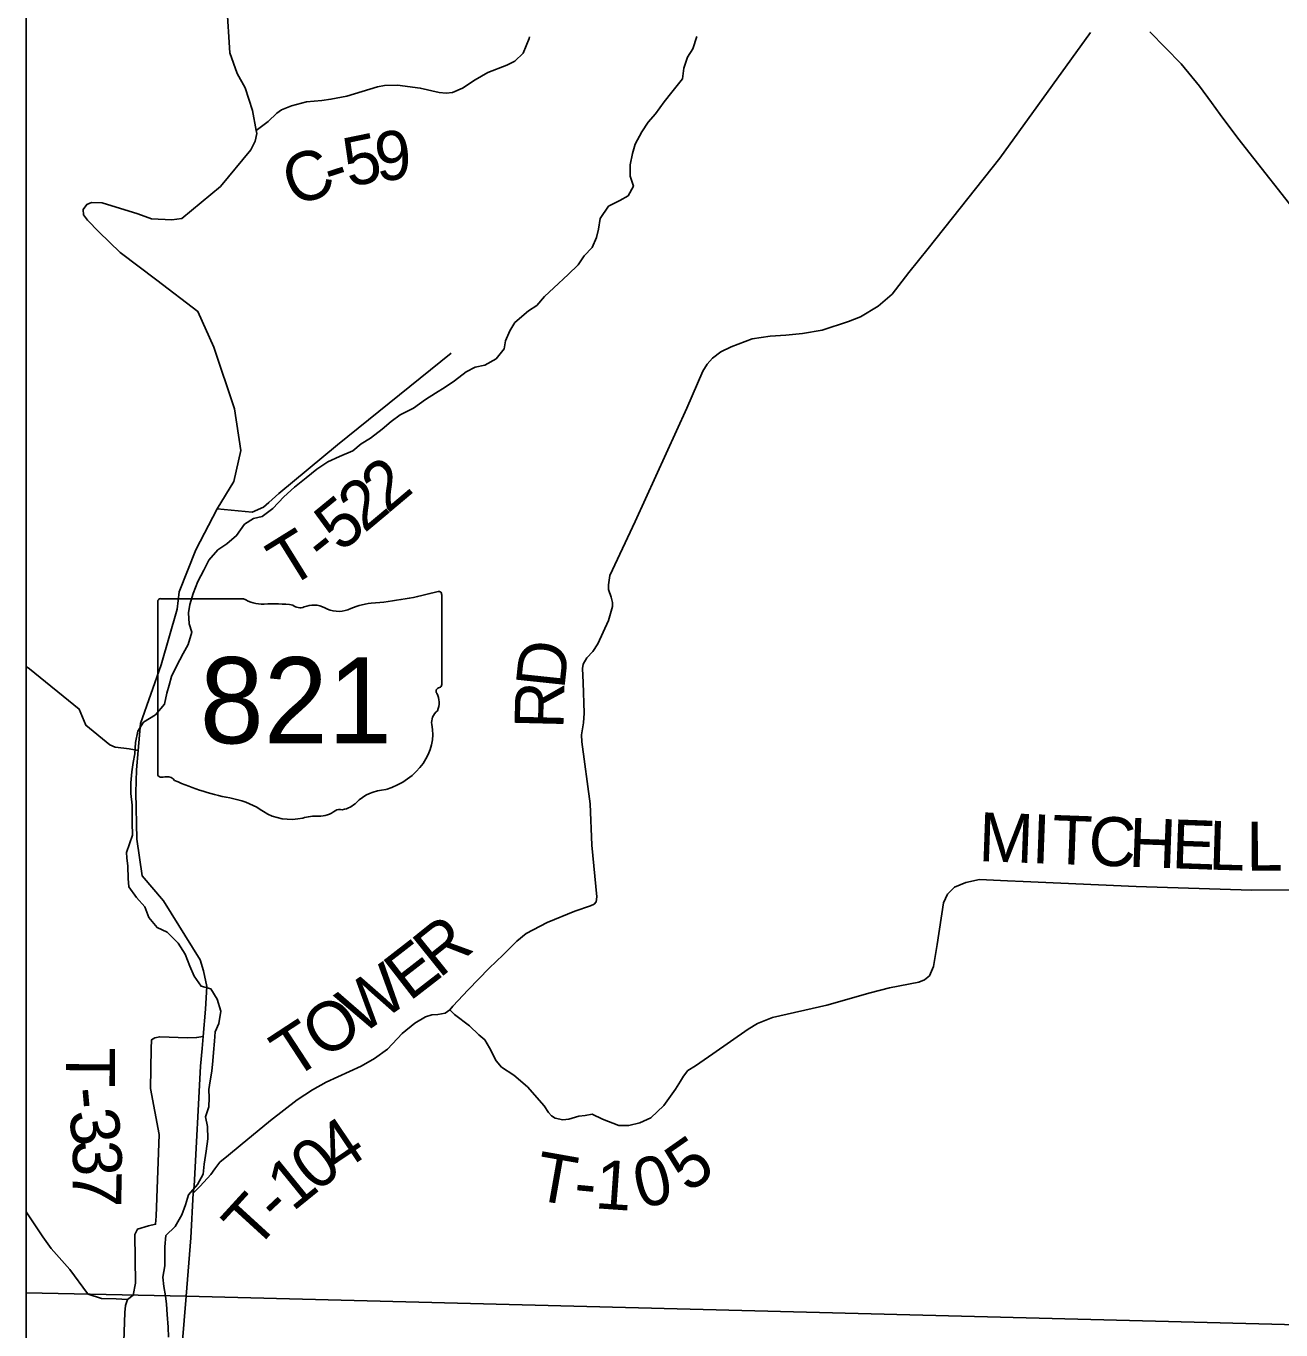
# Model space of a CAD drawing. Extents: x -22 to 431, y -18 to 160.
# Drawn here: x -8.719 to -7.263, y 17.085 to 18.598 of the extents above; entities that cross this region are included whole.
import ezdxf

# ---------------------------------------------------------------- set-up
doc = ezdxf.new("R2010")
doc.units = 0
for name, color, linetype in [('GM_X_Adjacent_County_Text', 7, 'Continuous'), ('GM_X_Airport_Location_Class_2', 7, 'Continuous'), ('GM_X_City_Street', 7, 'Continuous'), ('GM_X_City_Street_Text', 7, 'Continuous'), ('GM_X_Major_River_Text', 7, 'Continuous'), ('GM_X_Minor_River', 7, 'Continuous'), ('GM_X_Minor_River_Text', 7, 'Continuous'), ('GM_X_Rail_Line', 7, 'Continuous'), ('GM_X_Section', 7, 'Continuous')]:
    doc.layers.add(name, color=color, linetype=linetype)

msp = doc.modelspace()

# ---------------------------------------------------------------- linework, layer by layer
at = {"layer": 'GM_X_Adjacent_County_Text'}
for points in [[(-8.452, 18.4766), (-8.4382, 18.4871), (-8.4281, 18.4967), (-8.4228, 18.5009), (-8.4111, 18.5055), (-8.3937, 18.5102), (-8.3759, 18.5115), (-8.3653, 18.5131), (-8.3468, 18.5166), (-8.3113, 18.5275), (-8.303, 18.5291), (-8.2882, 18.5292), (-8.2617, 18.526), (-8.2397, 18.5209), (-8.2317, 18.5202), (-8.2242, 18.521), (-8.2125, 18.526), (-8.1978, 18.5356), (-8.1831, 18.5441), (-8.1612, 18.5526), (-8.1517, 18.5573), (-8.1423, 18.5664), (-8.1352, 18.5835), (-8.1348, 18.5855)], [(-6.8014, 18.0527), (-6.8014, 18.0528), (-6.8034, 18.0575), (-6.8042, 18.0624), (-6.8028, 18.0825), (-6.8187, 18.0839), (-6.946, 18.0918), (-6.9968, 18.095), (-7.0127, 18.099), (-7.0241, 18.1043), (-7.0435, 18.1223), (-7.1077, 18.2034), (-7.1677, 18.281), (-7.2342, 18.3681), (-7.3129, 18.468), (-7.3331, 18.4955), (-7.3434, 18.5091), (-7.3572, 18.5283), (-7.3786, 18.5543), (-7.4147, 18.5914)]]:
    msp.add_lwpolyline(points, dxfattribs=at)
at = {"layer": 'GM_X_Airport_Location_Class_2'}
for p, q in [((-8.5632, 17.9334), (-8.4666, 17.9334)), ((-8.2368, 17.9383), (-8.2368, 17.8337)), ((-8.5664, 17.9299), (-8.5664, 17.7298)), ((-8.5664, 17.7298), (-8.5664, 17.9299)), ((-8.5664, 17.7298), (-8.5664, 17.9299)), ((-8.2369, 17.8337), (-8.2368, 17.8337))]:
    msp.add_line(p, q, dxfattribs=at)
for centre, major_axis, start_param, end_param in [((-8.5626, 17.9304), (0.00382, 0), 1.712693, 3.28349), ((-8.4437, 17.9566), (0.037, 0), 4.042523, 4.731795), ((-8.3542, 18.2062), (0.3495, 0), 4.814394, 5.042369), ((-8.2405, 17.9388), (0.00367, 0), 6.141152, 7.989035), ((-8.4314, 17.821), (0.133, 0), 1.404758, 1.657858), ((-8.4012, 17.9314), (0.0107, 0), 3.836095, 5.185415), ((-8.3855, 17.9083), (0.0222, 0), 0.950623, 2.079405), ((-8.3568, 17.94), (0.0267, 0), 4.081561, 5.145723), ((-8.3096, 17.8723), (0.0703, 0), 1.699011, 2.107814), ((-8.2377, 17.826), (0.00568, 0), 1.883978, 3.671073), ((-8.2407, 17.8332), (0.00393, 0), 5.05454, 6.418171), ((-8.2738, 17.8127), (0.0341, 0), 5.934695, 6.695948), ((-8.2237, 17.7898), (0.0248, 0), 2.387724, 3.262537), ((-8.3346, 17.7765), (0.0874, 0), 5.101752, 6.440018), ((-8.5626, 17.7294), (0.00385, 0), 3.00124, 4.508301), ((-8.562, 17.7498), (0.0294, 0), 4.665946, 4.897461), ((-8.556, 17.7183), (0.0106, 0), 0.519207, 1.627899), ((-8.4222, 17.8981), (0.2524, 0), 4.195997, 4.488961), ((-8.2978, 17.6736), (0.0479, 0), 1.647645, 2.488434), ((-8.4974, 17.6399), (0.079, 0), 0.823519, 1.323587), ((-8.3584, 17.7104), (0.0282, 0), 4.937069, 5.64225), ((-8.412, 17.7173), (0.0501, 0), 4.026481, 4.996735), ((-8.3831, 17.6481), (0.0412, 0), 1.495662, 1.94098), ((-8.3794, 17.7023), (0.0267, 0), 4.691044, 5.507374), ((-8.3552, 17.6829), (0.00752, 0), 1.147584, 2.315152)]:
    msp.add_ellipse(centre, major_axis=major_axis, ratio=0.8, start_param=start_param, end_param=end_param, dxfattribs=at)
at = {"layer": 'GM_X_Major_River_Text'}
for p, q in [((-8.5332, 17.1237), (-8.7192, 17.1279)), ((-7.1011, 17.087), (-8.5332, 17.1237))]:
    msp.add_line(p, q, dxfattribs=at)
at = {"layer": 'GM_X_Minor_River'}
for points in [[(-8.6026, 17.6387), (-8.5958, 17.6591), (-8.5962, 17.6731), (-8.5959, 17.6834), (-8.5959, 17.6936), (-8.5975, 17.7072), (-8.5975, 17.7197), (-8.5964, 17.7326), (-8.5949, 17.7433), (-8.593, 17.7535), (-8.5923, 17.7664), (-8.5893, 17.7797), (-8.5829, 17.7899), (-8.5689, 17.7987), (-8.5584, 17.8109), (-8.5558, 17.8238), (-8.5531, 17.8332), (-8.5505, 17.8431), (-8.5445, 17.8549), (-8.537, 17.8697), (-8.5309, 17.8803), (-8.5268, 17.8944), (-8.5299, 17.9042), (-8.5307, 17.9171), (-8.5292, 17.9266), (-8.5254, 17.9395), (-8.5198, 17.9535), (-8.513, 17.9664), (-8.507, 17.9782), (-8.4968, 17.99), (-8.4862, 17.9972), (-8.4749, 18.0067), (-8.4655, 18.02), (-8.4553, 18.0265), (-8.4451, 18.0288), (-8.4326, 18.038), (-8.4201, 18.0517), (-8.4077, 18.0627), (-8.3941, 18.0737), (-8.3816, 18.0836), (-8.3691, 18.0924), (-8.3555, 18.0985), (-8.34, 18.105), (-8.3302, 18.113), (-8.3196, 18.1195), (-8.306, 18.1302), (-8.2955, 18.1389), (-8.2849, 18.1469), (-8.2694, 18.1545), (-8.2554, 18.1645), (-8.2441, 18.1721), (-8.2327, 18.1789), (-8.2221, 18.1862), (-8.2085, 18.1965), (-8.198, 18.2022), (-8.1866, 18.2045), (-8.1737, 18.2117), (-8.1643, 18.2232), (-8.1628, 18.2326), (-8.1576, 18.2444), (-8.1519, 18.2539), (-8.1361, 18.2676), (-8.1262, 18.2737), (-8.1175, 18.284), (-8.1066, 18.2942), (-8.09, 18.3098), (-8.0783, 18.3209), (-8.0715, 18.3315), (-8.0621, 18.341), (-8.0572, 18.3524), (-8.0549, 18.3623), (-8.0527, 18.3748), (-8.0433, 18.3889), (-8.03, 18.3957), (-8.0202, 18.4011), (-8.0142, 18.4121), (-8.018, 18.4238), (-8.018, 18.4371), (-8.0154, 18.45), (-8.0124, 18.461), (-8.0045, 18.4754), (-7.997, 18.4864), (-7.9887, 18.4963), (-7.9785, 18.51), (-7.9698, 18.5214), (-7.9574, 18.5366), (-7.9559, 18.5491), (-7.9514, 18.562), (-7.9454, 18.5715), (-7.9405, 18.5857)], [(-8.5539, 17.0762), (-8.5543, 17.088), (-8.5555, 17.1024), (-8.5563, 17.1145), (-8.5575, 17.1243), (-8.5594, 17.1349), (-8.5606, 17.1459), (-8.5583, 17.1592), (-8.558, 17.1687), (-8.558, 17.1812), (-8.5569, 17.1941), (-8.546, 17.2047), (-8.5385, 17.2184), (-8.5343, 17.2298), (-8.5306, 17.2416), (-8.5204, 17.2534), (-8.5136, 17.2655), (-8.5125, 17.2769), (-8.5103, 17.2921), (-8.5084, 17.3065), (-8.5085, 17.3209), (-8.5108, 17.3319), (-8.507, 17.3436), (-8.5067, 17.3542), (-8.5071, 17.3637), (-8.5056, 17.3736), (-8.5037, 17.385), (-8.5026, 17.3971), (-8.5015, 17.4066), (-8.5004, 17.4198), (-8.4997, 17.4305), (-8.4956, 17.4403), (-8.4933, 17.4548), (-8.4975, 17.4684), (-8.5048, 17.4805), (-8.5161, 17.4835), (-8.5241, 17.4952), (-8.5291, 17.5069), (-8.5344, 17.5209), (-8.5428, 17.5334), (-8.5553, 17.5463), (-8.5671, 17.5519), (-8.5766, 17.5633), (-8.5815, 17.5758), (-8.591, 17.5867), (-8.5998, 17.5988), (-8.6006, 17.6087), (-8.601, 17.6231), (-8.6022, 17.6325), (-8.6026, 17.6387)]]:
    msp.add_lwpolyline(points, dxfattribs=at)
at = {"layer": 'GM_X_Minor_River_Text'}
for points in [[(-8.5251, 17.2435), (-8.517, 17.2516), (-8.5046, 17.2649), (-8.5001, 17.2718), (-8.4941, 17.2794), (-8.4843, 17.2875), (-8.4708, 17.2986), (-8.4354, 17.3277), (-8.4045, 17.3518), (-8.3868, 17.3633), (-8.3709, 17.3722), (-8.3438, 17.3845), (-8.3302, 17.3907), (-8.3147, 17.3999), (-8.2997, 17.4107), (-8.2827, 17.4286), (-8.2681, 17.4409), (-8.2556, 17.4482), (-8.2481, 17.4502), (-8.2413, 17.4506), (-8.2326, 17.4525), (-8.2273, 17.456), (-8.2239, 17.4606), (-8.2059, 17.4793), (-8.1818, 17.5045), (-8.1656, 17.5202), (-8.1495, 17.5359), (-8.1386, 17.5447), (-8.1144, 17.5574), (-8.0823, 17.5706), (-8.0642, 17.5768), (-8.06, 17.5787), (-8.0574, 17.5814), (-8.0567, 17.5874), (-8.0624, 17.6473), (-8.0646, 17.6951), (-8.0742, 17.7671), (-8.0747, 17.7754), (-8.0721, 17.7891), (-8.0714, 17.8005), (-8.0725, 17.8361), (-8.0733, 17.8524), (-8.0726, 17.8574), (-8.0685, 17.8646), (-8.0613, 17.8719), (-8.0554, 17.881), (-8.043, 17.908), (-8.0386, 17.9244), (-8.0387, 17.9289), (-8.0402, 17.935), (-8.0433, 17.9441), (-8.0433, 17.9494), (-8.0415, 17.9604), (-8.0121, 18.0228), (-7.9524, 18.1545), (-7.9338, 18.1975), (-7.9285, 18.2056), (-7.9225, 18.2124), (-7.9127, 18.2197), (-7.9007, 18.2255), (-7.8765, 18.2348), (-7.8557, 18.238), (-7.8375, 18.2393), (-7.8182, 18.2413), (-7.7952, 18.2449), (-7.7646, 18.255), (-7.7506, 18.2604), (-7.7302, 18.2727), (-7.7141, 18.2869), (-7.6945, 18.3121), (-7.672, 18.34), (-7.5891, 18.4445), (-7.4838, 18.5904)], [(-8.4376, 18.0449), (-8.426, 18.0555), (-8.3576, 18.1119), (-8.2979, 18.1602), (-8.2259, 18.2185)], [(-8.4974, 18.0375), (-8.4569, 18.0338), (-8.4435, 18.0396), (-8.4376, 18.0449)], [(-8.5891, 17.7573), (-8.5996, 17.7591), (-8.6058, 17.7597), (-8.6156, 17.7609), (-8.6221, 17.7639), (-8.6499, 17.7864), (-8.6575, 17.8053), (-8.7152, 17.8519), (-8.7192, 17.8545)], [(-8.2273, 17.456), (-8.2219, 17.4507), (-8.2044, 17.4376), (-8.1938, 17.4271), (-8.1869, 17.4214), (-8.1812, 17.412), (-8.1735, 17.3969), (-8.1674, 17.3897), (-8.1529, 17.3804), (-8.1373, 17.3668), (-8.1178, 17.3446), (-8.1129, 17.3371), (-8.1094, 17.3333), (-8.1052, 17.3303), (-8.0961, 17.3285), (-8.0893, 17.3293), (-8.0776, 17.3328), (-8.0701, 17.3336), (-8.0621, 17.3352), (-8.0503, 17.3292), (-8.031, 17.3221), (-8.0196, 17.3219), (-8.0068, 17.325), (-7.9939, 17.3308), (-7.9789, 17.3453), (-7.9654, 17.364), (-7.9598, 17.3735), (-7.956, 17.3793), (-7.9512, 17.3857), (-7.9421, 17.3911), (-7.9221, 17.4053), (-7.8811, 17.4337), (-7.8701, 17.4402), (-7.8528, 17.4472), (-7.7897, 17.4617), (-7.7394, 17.4758), (-7.7171, 17.4817), (-7.6831, 17.4884), (-7.6763, 17.4911), (-7.6706, 17.4957), (-7.6658, 17.5064), (-7.6618, 17.5322), (-7.6542, 17.5804), (-7.6497, 17.5903), (-7.6414, 17.5987), (-7.6286, 17.6041), (-7.6127, 17.6073), (-7.5802, 17.606), (-7.562, 17.605), (-7.4306, 17.5993), (-7.2969, 17.595), (-7.1901, 17.5959)], [(-8.5136, 17.4253), (-8.5212, 17.4239), (-8.5318, 17.4237), (-8.5641, 17.425), (-8.5697, 17.4238), (-8.5735, 17.4214), (-8.574, 17.4108), (-8.5748, 17.3649), (-8.5648, 17.3115), (-8.5681, 17.2168), (-8.5689, 17.2074), (-8.5771, 17.2056), (-8.5899, 17.2015), (-8.5928, 17.1956), (-8.592, 17.1391), (-8.5948, 17.1251), (-8.6016, 17.1201)], [(-8.6478, 17.1269), (-8.6685, 17.1548), (-8.6901, 17.1793), (-8.6999, 17.1927), (-8.7192, 17.2218)], [(-8.6016, 17.1201), (-8.6146, 17.1209), (-8.6318, 17.1213), (-8.6473, 17.1263), (-8.6478, 17.1269)], [(-8.5406, 17.0312), (-8.5912, 17.0342), (-8.607, 17.0381), (-8.6047, 17.105), (-8.6036, 17.1132), (-8.6016, 17.1201)]]:
    msp.add_lwpolyline(points, dxfattribs=at)
at = {"layer": 'GM_X_Rail_Line'}
msp.add_lwpolyline([(-8.5381, 17.0675), (-8.5332, 17.1237), (-8.5281, 17.1917), (-8.5251, 17.2435), (-8.5239, 17.2514), (-8.5168, 17.3908), (-8.5147, 17.4114), (-8.5136, 17.4253), (-8.511, 17.4569), (-8.5094, 17.4833), (-8.5131, 17.5014), (-8.5171, 17.5142), (-8.5597, 17.5827), (-8.5844, 17.6118), (-8.5907, 17.6543), (-8.5916, 17.7086), (-8.5911, 17.7348), (-8.5891, 17.7573), (-8.5862, 17.7884), (-8.5622, 17.8568), (-8.5439, 17.9211), (-8.5413, 17.9415), (-8.5221, 17.9899), (-8.4974, 18.0375), (-8.478, 18.0695), (-8.4698, 18.1052), (-8.4772, 18.1538), (-8.5014, 18.2254), (-8.5197, 18.2667), (-8.5673, 18.3029), (-8.6099, 18.335), (-8.6347, 18.3592), (-8.648, 18.3728), (-8.6525, 18.3788), (-8.6529, 18.3849), (-8.6488, 18.391), (-8.6431, 18.3933), (-8.631, 18.393), (-8.5896, 18.3799), (-8.5737, 18.3743), (-8.5499, 18.3732), (-8.5385, 18.3748), (-8.4934, 18.4119), (-8.4584, 18.4543), (-8.4532, 18.4642), (-8.4514, 18.4733), (-8.452, 18.4766), (-8.4565, 18.5001), (-8.4649, 18.5263), (-8.4741, 18.5429), (-8.4826, 18.5668), (-8.4862, 18.6218)], dxfattribs=at)
at = {"layer": 'GM_X_Section'}
msp.add_line((-8.7192, 14.1345), (-8.7192, 20.9345), dxfattribs=at)

# ---------------------------------------------------------------- texts
at = {"layer": 'GM_X_Airport_Location_Class_2'}
msp.add_text('821', height=0.1, dxfattribs=at).set_placement((-8.5176, 17.7655))
at = {"layer": 'GM_X_City_Street'}
for s, rotation, p in [('9', 5.2261, (-8.3119, 18.4177)), ('5', 11.5896, (-8.3445, 18.4109)), ('C', 21.1349, (-8.4078, 18.3875)), ('-', 17.9532, (-8.3651, 18.4041))]:
    msp.add_text(s, height=0.0568, rotation=rotation, dxfattribs=at).set_placement(p)
at = {"layer": 'GM_X_City_Street_Text'}
for s, rotation, p in [('2', 40.0855, (-8.2997, 18.0314)), ('2', 39.9316, (-8.3266, 18.0088)), ('5', 39.4328, (-8.3541, 17.9862)), ('T', 31.87, (-8.415, 17.9445)), ('-', 38.7111, (-8.3729, 17.9712)), ('D', 83.9418, (-8.0945, 17.8272)), ('R', 88.5909, (-8.0956, 17.7817)), ('M', 357.8996, (-7.6142, 17.6288)), ('I', 357.8964, (-7.5525, 17.6265)), ('T', 357.8987, (-7.5292, 17.6257)), ('C', 357.8997, (-7.4868, 17.6241)), ('H', 357.8976, (-7.4401, 17.6224)), ('E', 357.9068, (-7.3901, 17.6206)), ('L', 358.331, (-7.3472, 17.619)), ('L', 0.2264, (-7.3027, 17.6177)), ('R', 38.8205, (-8.2397, 17.4919)), ('E', 37.779, (-8.2742, 17.4652)), ('W', 34.4701, (-8.3314, 17.4258)), ('O', 33.1778, (-8.3744, 17.3977)), ('T', 33.1825, (-8.41, 17.3744)), ('T', 269.5586, (-8.6726, 17.4129)), ('-', 275.0908, (-8.6726, 17.3644)), ('3', 278.5086, (-8.6701, 17.3375)), ('4', 33.9888, (-8.3564, 17.2645)), ('3', 270.6974, (-8.6651, 17.3049)), ('0', 38.9321, (-8.3825, 17.2432)), ('5', 35.045, (-7.951, 17.2428)), ('T', 349.9719, (-8.1314, 17.2364)), ('0', 13.4942, (-8.0062, 17.2251)), ('1', 39.0759, (-8.4097, 17.2212)), ('1', 355.9871, (-8.0599, 17.226)), ('7', 268.6989, (-8.6647, 17.2705)), ('-', 354.5167, (-8.0847, 17.2284)), ('T', 47.607, (-8.4537, 17.1754)), ('-', 43.1396, (-8.4259, 17.2059))]:
    msp.add_text(s, height=0.0568, rotation=rotation, dxfattribs=at).set_placement(p)

doc.saveas('drawing.dxf')
